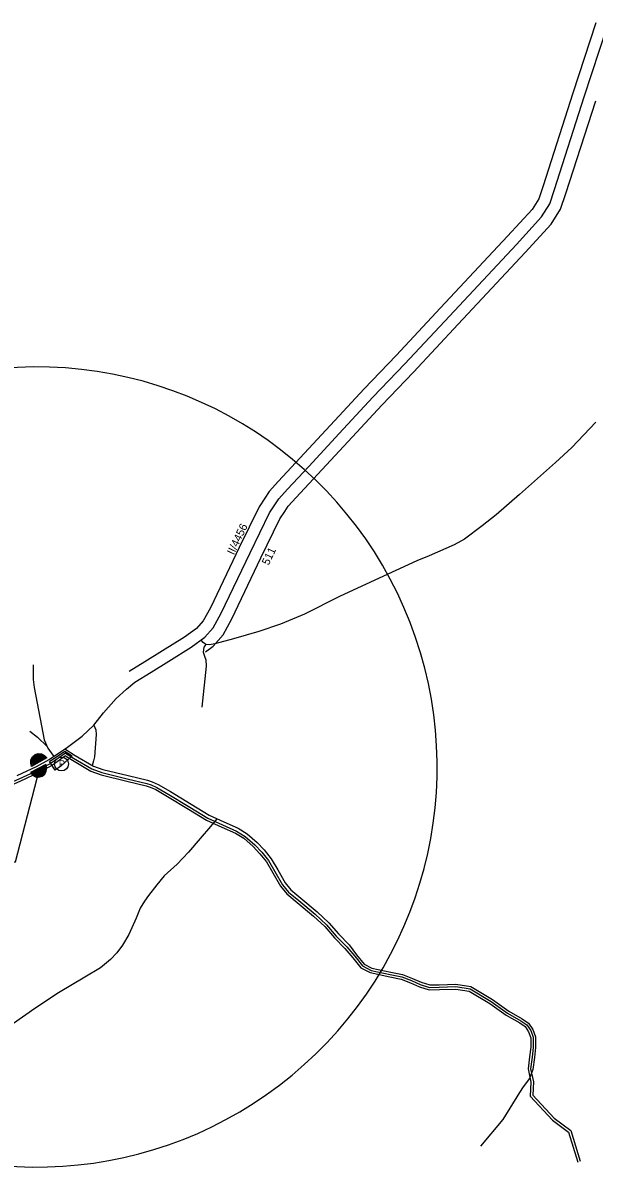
# Model space of a CAD drawing. Extents: x -547395 to -536032, y -1096268 to -1086572.
# Drawn here: x -544029 to -543316, y -1094854 to -1093424 of the extents above; entities that cross this region are included whole.
import ezdxf

# ---------------------------------------------------------------- set-up
doc = ezdxf.new("R2010")
doc.units = 0
for name, color, linetype in [('Vrstva 12', 7, 'Continuous'), ('Vrstva 29', 7, 'Continuous'), ('Vrstva 64', 7, 'Continuous'), ('Vrstva 66', 7, 'Continuous'), ('Vrstva 7', 7, 'Continuous'), ('Vrstva 70', 7, 'Continuous'), ('Vrstva 73', 7, 'Continuous'), ('Vrstva 76', 7, 'Continuous'), ('Vrstva 8', 7, 'Continuous')]:
    doc.layers.add(name, color=color, linetype=linetype)

msp = doc.modelspace()

# ---------------------------------------------------------------- linework, layer by layer
at = {"layer": 'Vrstva 12'}
for points in [[(-543313.5, -1093922.9), (-543343.4, -1093954.4), (-543364, -1093973.2), (-543408.9, -1094013.1), (-543438, -1094038.8), (-543455.6, -1094052.5), (-543477.4, -1094068.9), (-543490.2, -1094076), (-543521.6, -1094090), (-543537, -1094096.2), (-543589.3, -1094120.2), (-543633.5, -1094140.7), (-543677.1, -1094162.9), (-543707.2, -1094175.4), (-543734.2, -1094184.5), (-543765.8, -1094193.6), (-543789, -1094199.7), (-543795.9, -1094201.3), (-543800.2, -1094200.7), (-543803.6, -1094198.1), (-543806.4, -1094195.1)], [(-543800.2, -1094200.7), (-543803, -1094204.2), (-543803.9, -1094210.1), (-543802.1, -1094215.3), (-543800.5, -1094219.9), (-543799.8, -1094227.9), (-543805.3, -1094279)], [(-544020.1, -1094309.1), (-544010.6, -1094316.7), (-543998.5, -1094328.2)], [(-543786.5, -1094418.4), (-543794.7, -1094428.2), (-543807.3, -1094443.1), (-543822, -1094460.4), (-543836.3, -1094475.1), (-543852.2, -1094489.9), (-543861.5, -1094501.1), (-543871.9, -1094514.5), (-543877, -1094521.5), (-543882.3, -1094530.3), (-543887.3, -1094542.5), (-543896.5, -1094563.1), (-543904.6, -1094576.5), (-543911.5, -1094586.2), (-543919.4, -1094594.2), (-543932, -1094604.7), (-543951.6, -1094616.4), (-543984.2, -1094636.1), (-544014, -1094655.4), (-544040.3, -1094674.4)], [(-543621.6, -1094575.9), (-543612.1, -1094588.6), (-543602.9, -1094600.1), (-543593.1, -1094605.1), (-543569.6, -1094610), (-543554.7, -1094613.2), (-543542.4, -1094617.9), (-543531.6, -1094622.8), (-543520.9, -1094626.2), (-543509, -1094625.9), (-543488.2, -1094625.3), (-543469.4, -1094628.3), (-543442.6, -1094644.3), (-543422.1, -1094658.9), (-543405.5, -1094668.4), (-543397.4, -1094673.8), (-543392.1, -1094681.9), (-543388.8, -1094691.1), (-543388.8, -1094704.5), (-543390.2, -1094716.9), (-543392.2, -1094731.8), (-543396.5, -1094742.9), (-543404.2, -1094753.4), (-543409, -1094760.5), (-543429.6, -1094794.2), (-543457.7, -1094827.8)]]:
    msp.add_lwpolyline(points, dxfattribs=at)
at = {"layer": 'Vrstva 29'}
msp.add_lwpolyline([(-543967.3, -1094339.7), (-543981.3, -1094352.8), (-543988.5, -1094357.9), (-543995.4, -1094347), (-543976.5, -1094334.1)], close=True, dxfattribs=at)
msp.add_circle((-543980.5, -1094350), 8.68, dxfattribs=at)
at = {"layer": 'Vrstva 64'}
msp.add_arc((-544011.6, -1094353.8), 500, 235.7806, 162.0112, dxfattribs=at)
at = {"layer": 'Vrstva 66'}
for points in [[(-543313.4, -1093423.8), (-543342.3, -1093511.8), (-543379.4, -1093627.5), (-543384.8, -1093643.6), (-543393.2, -1093657), (-543423.8, -1093690.5), (-543507.3, -1093780), (-543562.8, -1093839.7), (-543602.6, -1093881.1), (-543644.8, -1093926.6), (-543682.9, -1093967.9), (-543709.7, -1093996.6), (-543721.3, -1094009.5), (-543726.6, -1094017.8), (-543733.9, -1094028.6), (-543758.7, -1094079.5), (-543794.5, -1094154.7), (-543803.6, -1094171.1), (-543811.9, -1094180.5), (-543827, -1094191.7), (-543854.3, -1094208.8), (-543876.5, -1094222.4), (-543896.2, -1094234.4)], [(-543800.9, -1094209.7), (-543791.4, -1094202.7), (-543778.9, -1094188.4), (-543767.8, -1094168.5), (-543731.6, -1094092.5), (-543707.9, -1094043.7), (-543701.6, -1094034.3), (-543697.4, -1094027.7), (-543687.6, -1094016.8), (-543660.9, -1093988.3), (-543622.8, -1093946.9), (-543580.8, -1093901.7), (-543541, -1093860.3), (-543485.3, -1093800.4), (-543401.7, -1093710.8), (-543369.2, -1093675.2), (-543357.5, -1093656.5), (-543350.9, -1093636.9), (-543313.7, -1093521.1)]]:
    msp.add_lwpolyline(points, dxfattribs=at)
at = {"layer": 'Vrstva 7'}
msp.add_lwpolyline([(-544035.9, -1094364.5), (-544011.6, -1094353.2), (-543996.1, -1094344.6), (-543973.2, -1094328.8), (-543954.6, -1094315.3), (-543940.1, -1094301.6), (-543928.2, -1094286.1), (-543912.1, -1094268), (-543899.6, -1094256.7), (-543889.2, -1094247.7), (-543868.7, -1094235.2), (-543846.4, -1094221.6), (-543818.6, -1094204.1), (-543801.7, -1094191.6), (-543791.2, -1094179.7), (-543781.1, -1094161.6), (-543745.2, -1094086), (-543720.9, -1094036.2), (-543714.1, -1094026), (-543709.3, -1094018.6), (-543698.6, -1094006.7), (-543671.9, -1093978.1), (-543633.8, -1093936.8), (-543591.7, -1093891.4), (-543551.9, -1093850), (-543496.3, -1093790.2), (-543412.7, -1093700.6), (-543381.2, -1093666.1), (-543371.1, -1093650.1), (-543365.2, -1093632.2), (-543328, -1093516.4), (-543299.2, -1093428.7)], dxfattribs=at)
at = {"layer": 'Vrstva 70'}
for points in [[(-543975.5, -1094336.5), (-543993.5, -1094348.9), (-544009.3, -1094357.7), (-544033.9, -1094369.1), (-544071.1, -1094385.2), (-544093.2, -1094394.7)], [(-543975.4, -1094340), (-543991.9, -1094351.4), (-544007.9, -1094360.4), (-544032.7, -1094371.8), (-544070, -1094388), (-544092, -1094397.4)], [(-543975.5, -1094336.5), (-543965.5, -1094342.6), (-543942.5, -1094356.2), (-543930.1, -1094360.6), (-543898.4, -1094368.4), (-543874.1, -1094374.3), (-543868.8, -1094376), (-543861.5, -1094379.4), (-543846.7, -1094388), (-543820.5, -1094403.8), (-543798, -1094417.6), (-543779.4, -1094426), (-543762.1, -1094434), (-543751.3, -1094440.5), (-543739.2, -1094451.2), (-543730.5, -1094460.1), (-543722.2, -1094470.8), (-543714.1, -1094484.4), (-543704.5, -1094501), (-543697.2, -1094510.1), (-543684.4, -1094520.8), (-543664, -1094537.7), (-543649.6, -1094551.2), (-543637.5, -1094565.1), (-543624.5, -1094578.7)], [(-543975.4, -1094340), (-543967, -1094345.2), (-543943.8, -1094359), (-543930.9, -1094363.5), (-543899.1, -1094371.3), (-543874.9, -1094377.2), (-543869.9, -1094378.8), (-543862.9, -1094382), (-543848.2, -1094390.6), (-543822.1, -1094406.3), (-543799.4, -1094420.2), (-543780.6, -1094428.8), (-543763.5, -1094436.6), (-543753.1, -1094442.9), (-543741.2, -1094453.3), (-543732.8, -1094462.1), (-543724.6, -1094472.5), (-543716.7, -1094485.9), (-543707, -1094502.7), (-543699.4, -1094512.3), (-543686.3, -1094523.1), (-543666, -1094540), (-543651.8, -1094553.3), (-543639.7, -1094567.1), (-543626.7, -1094580.7)], [(-543626.7, -1094580.7), (-543616.8, -1094592.4), (-543606.8, -1094604.8), (-543595.1, -1094610.8), (-543570.8, -1094615.9), (-543556.4, -1094618.9), (-543544.7, -1094623.5), (-543533.7, -1094628.4), (-543521.7, -1094632.2), (-543508.8, -1094631.9), (-543488.5, -1094631.3), (-543471.5, -1094634), (-543445.9, -1094649.4), (-543425.4, -1094664), (-543408.6, -1094673.6), (-543401.8, -1094678.1), (-543397.5, -1094684.6), (-543394.8, -1094692.1), (-543394.8, -1094704.1), (-543396.2, -1094716.2), (-543398.1, -1094731.2), (-543394.5, -1094747.5), (-543395.4, -1094765.1), (-543367.5, -1094795), (-543347.5, -1094810), (-543336, -1094847.6)], [(-543624.5, -1094578.7), (-543614.5, -1094590.4), (-543604.8, -1094602.4), (-543594.1, -1094608), (-543570.2, -1094613), (-543555.6, -1094616), (-543543.5, -1094620.7), (-543532.7, -1094625.6), (-543521.3, -1094629.2), (-543508.9, -1094628.9), (-543488.3, -1094628.3), (-543470.5, -1094631.1), (-543444.3, -1094646.9), (-543423.7, -1094661.5), (-543407, -1094671), (-543399.6, -1094676), (-543394.8, -1094683.2), (-543391.8, -1094691.6), (-543391.8, -1094704.3), (-543393.2, -1094716.5), (-543395.1, -1094731), (-543391.5, -1094747.3), (-543392.3, -1094764), (-543365.5, -1094792.8), (-543344.9, -1094808.2), (-543333.2, -1094846.5)]]:
    msp.add_lwpolyline(points, dxfattribs=at)
at = {"layer": 'Vrstva 73'}
msp.add_lwpolyline([(-544035.9, -1094364.5), (-544011.6, -1094353.2), (-543996.1, -1094344.6), (-543973.2, -1094328.8), (-543954.6, -1094315.3), (-543940.1, -1094301.6), (-543928.2, -1094286.1), (-543912.1, -1094268), (-543899.6, -1094256.7), (-543889.2, -1094247.7), (-543868.7, -1094235.2), (-543846.4, -1094221.6), (-543818.6, -1094204.1), (-543801.7, -1094191.6), (-543791.2, -1094179.7), (-543781.1, -1094161.6), (-543745.2, -1094086), (-543720.9, -1094036.2), (-543714.1, -1094026), (-543709.3, -1094018.6), (-543698.6, -1094006.7), (-543671.9, -1093978.1), (-543633.8, -1093936.8), (-543591.7, -1093891.4), (-543551.9, -1093850), (-543496.3, -1093790.2), (-543412.7, -1093700.6), (-543381.2, -1093666.1), (-543371.1, -1093650.1), (-543365.2, -1093632.2), (-543328, -1093516.4), (-543299.2, -1093428.7)], dxfattribs=at)
at = {"layer": 'Vrstva 76'}
for points in [[(-544013.5, -1094338.3), (-544009.5, -1094337), (-544005.3, -1094337.4), (-544001.6, -1094339.3), (-543998.8, -1094342.5), (-544017.8, -1094353), (-544019, -1094348.9), (-544018.7, -1094344.7), (-544016.7, -1094341)], [(-544013.1, -1094339), (-544009.4, -1094337.8), (-544005.5, -1094338.1), (-544002.1, -1094339.9), (-544000.1, -1094342.3), (-544017.3, -1094351.8), (-544018.2, -1094348.8), (-544017.9, -1094345), (-544016.1, -1094341.5)], [(-544012.7, -1094339.7), (-544009.3, -1094338.6), (-544005.8, -1094338.9), (-544002.6, -1094340.6), (-544001.3, -1094342.1), (-544016.8, -1094350.6), (-544017.4, -1094348.8), (-544017.1, -1094345.2), (-544015.5, -1094342)], [(-544012.3, -1094340.4), (-544009.2, -1094339.4), (-544006, -1094339.7), (-544003.1, -1094341.2), (-544002.6, -1094341.8), (-544016.4, -1094349.4), (-544016.6, -1094348.7), (-544016.3, -1094345.4), (-544014.8, -1094342.5)], [(-544011.9, -1094341.1), (-544009.1, -1094340.2), (-544006.2, -1094340.5), (-544003.9, -1094341.7), (-544015.8, -1094348.2), (-544015.5, -1094345.6), (-544014.2, -1094343)], [(-544011.5, -1094341.9), (-544009, -1094341.1), (-544006.4, -1094341.3), (-544005.6, -1094341.7), (-544014.8, -1094346.8), (-544014.8, -1094345.9), (-544013.6, -1094343.5)], [(-544011.2, -1094342.6), (-544009, -1094341.9), (-544007.8, -1094342), (-544013.5, -1094345.1), (-544012.9, -1094344.1)], [(-544004.8, -1094365.3), (-544001.5, -1094362.7), (-543999.5, -1094359), (-543999, -1094354.8), (-544000.1, -1094350.7), (-544019.4, -1094360.6), (-544016.7, -1094363.9), (-544013.1, -1094365.9), (-544008.9, -1094366.4)], [(-544005.2, -1094364.5), (-544002.1, -1094362.1), (-544000.2, -1094358.7), (-543999.8, -1094354.9), (-544000.6, -1094351.9), (-544018.1, -1094360.8), (-544016.2, -1094363.3), (-544012.8, -1094365.2), (-544008.9, -1094365.6)], [(-544005.6, -1094363.8), (-544002.8, -1094361.6), (-544001, -1094358.5), (-544000.6, -1094354.9), (-544001.1, -1094353), (-544016.9, -1094361.1), (-544015.7, -1094362.6), (-544012.6, -1094364.4), (-544009, -1094364.8)], [(-544005.9, -1094363.1), (-544003.4, -1094361.1), (-544001.8, -1094358.2), (-544001.4, -1094355), (-544001.6, -1094354.2), (-544015.7, -1094361.4), (-544015.2, -1094362), (-544012.3, -1094363.6), (-544009.1, -1094364)], [(-544006.3, -1094362.4), (-544004, -1094360.5), (-544002.6, -1094358), (-544002.3, -1094355.4), (-544014.3, -1094361.6), (-544012.1, -1094362.8), (-544009.1, -1094363.2)], [(-544006.7, -1094361.6), (-544004.6, -1094360), (-544003.3, -1094357.7), (-544003.2, -1094356.8), (-544012.6, -1094361.6), (-544011.8, -1094362), (-544009.2, -1094362.4)], [(-544007.1, -1094360.9), (-544005.2, -1094359.5), (-544004.7, -1094358.4), (-544010.4, -1094361.4), (-544009.3, -1094361.5)]]:
    msp.add_lwpolyline(points, close=True, dxfattribs=at)
msp.add_lwpolyline([(-544127.5, -1094472.3), (-544037.8, -1094472.3), (-544008.2, -1094356.5)], dxfattribs=at)
at = {"layer": 'Vrstva 8'}
for points in [[(-544016.1, -1094226.1), (-544015.8, -1094244.6), (-544014.6, -1094254.4), (-544005.6, -1094302.3), (-544002.1, -1094319.9), (-543997.6, -1094330.3), (-543993.4, -1094336.2), (-543990.3, -1094340.6)], [(-543940.1, -1094301.6), (-543937.6, -1094307.4), (-543937.4, -1094313.3), (-543939.5, -1094341), (-543940.4, -1094345.9), (-543942.3, -1094351.7)], [(-543976.5, -1094331.1), (-543963.4, -1094339.2), (-543940.8, -1094352.6), (-543928.9, -1094356.8), (-543897.4, -1094364.5), (-543873, -1094370.4), (-543867.4, -1094372.2), (-543859.7, -1094375.8), (-543844.6, -1094384.6), (-543818.5, -1094400.4), (-543796.2, -1094414), (-543777.7, -1094422.4), (-543760.2, -1094430.4), (-543748.9, -1094437.3), (-543736.4, -1094448.3), (-543727.5, -1094457.5), (-543718.8, -1094468.5), (-543710.7, -1094482.3), (-543701.2, -1094498.7), (-543694.3, -1094507.3), (-543681.8, -1094517.8), (-543661.3, -1094534.7), (-543646.8, -1094548.4), (-543634.6, -1094562.4), (-543621.6, -1094575.9)]]:
    msp.add_lwpolyline(points, dxfattribs=at)

# ---------------------------------------------------------------- texts
at = {"layer": 'Vrstva 29'}
msp.add_text('P', height=8.75, dxfattribs=at).set_placement((-543983.9, -1094354.1))
at = {"layer": 'Vrstva 7'}
msp.add_text('II/4456', height=10, rotation=64.5523, dxfattribs=at).set_placement((-543765.4, -1094089.5))
at = {"layer": 'Vrstva 73'}
msp.add_text('511', height=10, rotation=64.5523, dxfattribs=at).set_placement((-543722, -1094102.4))

doc.saveas('drawing.dxf')
